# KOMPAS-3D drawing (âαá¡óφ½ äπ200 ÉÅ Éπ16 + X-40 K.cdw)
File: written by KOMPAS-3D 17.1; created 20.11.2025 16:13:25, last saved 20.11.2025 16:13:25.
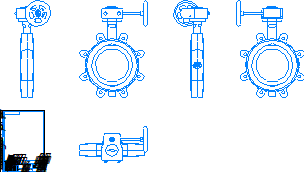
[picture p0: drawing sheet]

Sheet 1: A4, portrait

Title block, sheet 1: material: Сталь 20  ГОСТ 1050-2013; mass: 13,4; sheets: 1; sheet format: A4

Views: Вид 1, Спереди, Проекционный вид 2, Проекционный вид 3, Проекционный вид 4, Проекционный вид 5
Referenced files in \\adlc.lan\data\АДЛ_ПКД\3D-модели\ADL production\Дисковые поворотные затворы ГРАНВЭЛ\с резьбовыми проушинами с китайским редуктором Ру 16\KOMPAS 3D\: Гранвэл Ду200 РП Ру16 + X-40 K.m3d
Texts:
  Andrey
  АДЛ
Dimensions and other numbers on the sheet: 1:1; 1; 13,4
